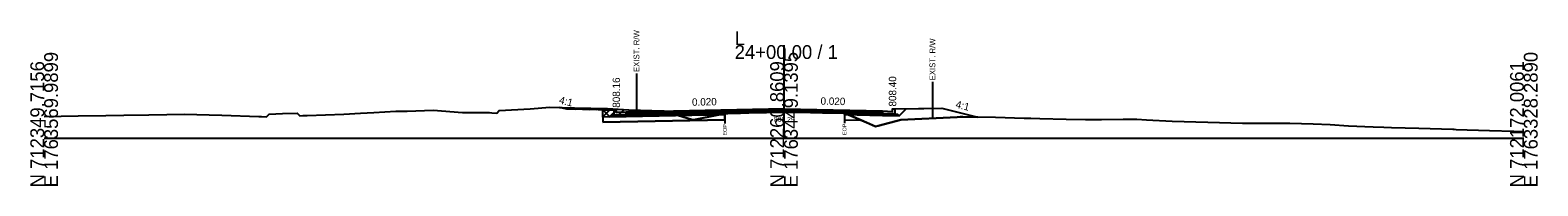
# Model space of a CAD drawing. Extents: x -26 to 5303, y -10 to 9578.
# Drawn here: x 997.2 to 1302.8, y 3990.3 to 4021.9 of the extents above; entities that cross this region are included whole.
import ezdxf

# ---------------------------------------------------------------- set-up
doc = ezdxf.new("R2010")
doc.units = 0
for name, color, linetype in [('Default', 7, 'Continuous'), ('Exist CMT Pavement', 7, 'Continuous'), ('Exist Cross Section Cell', 7, 'Continuous'), ('Exist XS Ground Line', 7, 'Continuous'), ('Old_Level_10', 7, 'Continuous'), ('Old_Level_3', 7, 'Continuous'), ('Prop CMT Conc Surface', 7, 'Continuous'), ('Prop CMT Concrete Structures', 7, 'Continuous'), ('Prop CMT Pvmt Course 1', 7, 'Continuous'), ('Prop CMT Pvmt Course 1 CG', 7, 'Continuous'), ('Prop CMT Pvmt Course 2', 7, 'Continuous'), ('Prop CMT Pvmt Course 3', 7, 'Continuous'), ('Prop CMT Pvmt Surface', 7, 'Continuous'), ('Prop CMT Slope Grass', 7, 'Continuous'), ('Prop CMT Subgrade Earthwork', 7, 'Continuous'), ('Prop Shade Light', 7, 'Continuous'), ('Prop XS Earthwork Shape', 7, 'Continuous'), ('Prop XS Hydro Elevations', 7, 'Continuous'), ('Prop XS SE Text', 7, 'Continuous'), ('Prop XS Side Slope Text', 7, 'Continuous'), ('Prop XS Wedging', 7, 'Continuous'), ('Scratch_Level_5', 7, 'Continuous')]:
    doc.layers.add(name, color=color, linetype=linetype)

msp = doc.modelspace()

# ---------------------------------------------------------------- linework, layer by layer
at = {"layer": 'Exist CMT Pavement'}
msp.add_lwpolyline([(1138.01, 4004.98), (1138.59, 4005), (1139.27, 4005.03), (1141.17, 4005.07), (1142.85, 4005.13), (1144.28, 4005.16), (1145.12, 4005.18), (1146.42, 4005.21), (1147.38, 4005.23), (1148.27, 4005.24), (1150, 4005.29), (1150.3, 4005.29), (1151.08, 4005.27), (1151.79, 4005.26), (1153.59, 4005.23), (1155.36, 4005.21), (1156.69, 4005.18), (1157.15, 4005.17), (1157.78, 4005.15), (1158.94, 4005.14), (1159.79, 4005.13), (1160.73, 4005.12), (1161.63, 4005.09), (1162.26, 4005.07), (1162.26, 4005.07)], dxfattribs=at)
at = {"layer": 'Exist Cross Section Cell'}
for p, q in [((1150, 4000), (1150, 4018.85)), ((1000, 4000), (1150, 4000)), ((1150, 4000), (1300, 4000))]:
    msp.add_line(p, q, dxfattribs=at)
at = {"layer": 'Exist XS Ground Line'}
msp.add_lwpolyline([(1000, 4004.41), (1006.9, 4004.51), (1012.49, 4004.61), (1016.17, 4004.67), (1021.2, 4004.73), (1024.9, 4004.78), (1028.36, 4004.82), (1036.02, 4004.66), (1043.49, 4004.41), (1044.04, 4004.38), (1045.11, 4004.34), (1045.65, 4004.85), (1048.33, 4004.98), (1051.32, 4005.04), (1051.82, 4004.54), (1052.42, 4004.57), (1053.32, 4004.61), (1060.77, 4004.88), (1064.13, 4005.03), (1066.82, 4005.2), (1071.28, 4005.46), (1073.6, 4005.47), (1078.88, 4005.67), (1084.8, 4005.2), (1090.28, 4005.16), (1090.73, 4005.13), (1091.78, 4005.08), (1092.28, 4005.58), (1098.51, 4005.95), (1102.52, 4006.28), (1107.49, 4006.15), (1114.2, 4005.99), (1118.54, 4005.74), (1125.55, 4005.5), (1131.24, 4003.79), (1131.65, 4003.68), (1137.45, 4004.88), (1138.01, 4004.98), (1138.59, 4005), (1139.27, 4005.03), (1141.17, 4005.07), (1141.93, 4005.09), (1144.28, 4005.16), (1145.12, 4005.18), (1146.42, 4005.21), (1147.38, 4005.23), (1148.27, 4005.24), (1150, 4005.29), (1150.3, 4005.29), (1151.08, 4005.27), (1151.79, 4005.26), (1153.59, 4005.23), (1155.36, 4005.21), (1156.69, 4005.18), (1157.78, 4005.15), (1158.94, 4005.14), (1159.79, 4005.13), (1160.73, 4005.12), (1161.63, 4005.09), (1162.26, 4005.07), (1166.73, 4003.13), (1168.57, 4002.38), (1169.09, 4002.51), (1173.66, 4003.68), (1185.08, 4004.26), (1185.74, 4004.3), (1186.28, 4004.29), (1192.9, 4004.23), (1198.7, 4004.02), (1200.05, 4004.02), (1201.89, 4003.97), (1207.2, 4003.85), (1211.11, 4003.79), (1214.36, 4003.79), (1218.78, 4003.86), (1221.51, 4003.82), (1223.52, 4003.72), (1228.67, 4003.43), (1235.94, 4003.21), (1242.97, 4003.04), (1248.35, 4003.04), (1252.54, 4003.02), (1257.28, 4002.89), (1260.76, 4002.76), (1264.43, 4002.5), (1269.43, 4002.27), (1271.59, 4002.2), (1273.18, 4002.16), (1278.74, 4002.03), (1285.59, 4001.79), (1285.9, 4001.78), (1286.31, 4001.76), (1293.05, 4001.51), (1298, 4001.4), (1300, 4001.34)], dxfattribs=at)
at = {"layer": 'Old_Level_10'}
for p, q in [((1120.09, 4013.09), (1120.09, 4005.69)), ((1180.09, 4011.41), (1180.09, 4004.01)), ((1138.01, 4004.98), (1138.01, 4002.93)), ((1162.26, 4005.07), (1162.26, 4003.02))]:
    msp.add_line(p, q, dxfattribs=at)
at = {"layer": 'Prop CMT Conc Surface'}
for points in [[(1116, 4005.16), (1116, 4005.66), (1115.5, 4005.66)], [(1118, 4005.28), (1116, 4005.16)], [(1170, 4005.52), (1172, 4005.4)], [(1172, 4005.4), (1172, 4005.9), (1172.5, 4005.9)]]:
    msp.add_lwpolyline(points, dxfattribs=at)
at = {"layer": 'Prop CMT Concrete Structures'}
for points in [[(1118, 4005.28), (1116, 4005.16), (1116, 4005.66), (1115.5, 4005.66)], [(1115.5, 4005.66), (1115.5, 4004.65), (1118, 4004.7)], [(1118, 4004.7), (1118, 4005.28)], [(1170, 4005.52), (1172, 4005.4), (1172, 4005.9), (1172.5, 4005.9)], [(1172.5, 4005.9), (1172.5, 4004.89), (1170, 4004.94)], [(1170, 4004.94), (1170, 4005.52)]]:
    msp.add_lwpolyline(points, dxfattribs=at)
at = {"layer": 'Prop CMT Pvmt Course 1'}
for points in [[(1150, 4005.92), (1118, 4005.28)], [(1118, 4005.03), (1138.01, 4005.43)], [(1118, 4005.28), (1118, 4005.03)], [(1138.01, 4005.43), (1150, 4005.67)], [(1138.01, 4005.43), (1138.01, 4005.43)], [(1150, 4005.67), (1150, 4005.92)], [(1150, 4005.92), (1170, 4005.52)], [(1150, 4005.67), (1150, 4005.67), (1150, 4005.67)], [(1162.26, 4005.43), (1150, 4005.67)], [(1170, 4005.27), (1162.26, 4005.43)], [(1162.26, 4005.43), (1162.26, 4005.43)], [(1170, 4005.52), (1170, 4005.27)]]:
    msp.add_lwpolyline(points, dxfattribs=at)
at = {"layer": 'Prop CMT Pvmt Course 1 CG'}
for points in [[(1118, 4004.7), (1115, 4004.64), (1114.66, 4004.3)], [(1118, 4004.37), (1118, 4004.7)], [(1170, 4004.94), (1173, 4004.88), (1173.34, 4004.54)], [(1170, 4004.61), (1170, 4004.94)], [(1173.34, 4004.54), (1170, 4004.61)], [(1114.66, 4004.3), (1118, 4004.37)]]:
    msp.add_lwpolyline(points, dxfattribs=at)
at = {"layer": 'Prop CMT Pvmt Course 2'}
for points in [[(1138.01, 4005.43), (1118, 4005.03)], [(1118, 4004.7), (1138.01, 4005.1)], [(1118, 4005.03), (1118, 4004.7)], [(1138.01, 4005.1), (1138.01, 4005.43)], [(1162.26, 4005.09), (1162.26, 4005.43)], [(1162.26, 4005.43), (1170, 4005.27)], [(1170, 4004.94), (1162.26, 4005.09)], [(1170, 4005.27), (1170, 4004.94)]]:
    msp.add_lwpolyline(points, dxfattribs=at)
at = {"layer": 'Prop CMT Pvmt Course 3'}
for points in [[(1138.01, 4005.1), (1118, 4004.7)], [(1118, 4004.37), (1138.01, 4004.77)], [(1118, 4004.7), (1118, 4004.37)], [(1138.01, 4004.77), (1138.01, 4005.1)], [(1162.26, 4005.09), (1170, 4004.94)], [(1162.26, 4004.76), (1162.26, 4005.09)], [(1170, 4004.61), (1162.26, 4004.76)], [(1170, 4004.94), (1170, 4004.61)]]:
    msp.add_lwpolyline(points, dxfattribs=at)
at = {"layer": 'Prop CMT Pvmt Surface'}
for points in [[(1150, 4005.92), (1118, 4005.28)], [(1150, 4005.92), (1170, 4005.52)]]:
    msp.add_lwpolyline(points, dxfattribs=at)
at = {"layer": 'Prop CMT Slope Grass'}
for points in [[(1115.5, 4005.66), (1106, 4005.85), (1104.5, 4006.23)], [(1172.5, 4005.9), (1182, 4006.09), (1189.32, 4004.26)]]:
    msp.add_lwpolyline(points, dxfattribs=at)
at = {"layer": 'Prop CMT Subgrade Earthwork'}
for p, q in [((1138.01, 4004.77), (1138.01, 4004.98)), ((1162.26, 4004.76), (1162.26, 4005.07))]:
    msp.add_line(p, q, dxfattribs=at)
for points in [[(1118, 4004.37), (1114.66, 4004.3), (1113.25, 4005.71)], [(1138.01, 4004.77), (1118, 4004.37)], [(1162.26, 4004.76), (1170, 4004.61)], [(1170, 4004.61), (1173.34, 4004.54), (1174.75, 4005.95)]]:
    msp.add_lwpolyline(points, dxfattribs=at)
at = {"layer": 'Prop Shade Light'}
for p, q in [((1128.61, 4004.58), (1118, 4004.37)), ((1138.01, 4004.77), (1136.78, 4004.74)), ((1138.01, 4004.77), (1138.01, 4003.73)), ((1138.01, 4003.73), (1138.01, 4004.77)), ((1162.26, 4004.76), (1162.26, 4003.72)), ((1162.26, 4004.76), (1162.26, 4003.72)), ((1163.01, 4004.75), (1162.26, 4004.76)), ((1165.51, 4003.66), (1163.01, 4004.75)), ((1114.66, 4004.3), (1113.25, 4004.27)), ((1113.25, 4004.27), (1113.25, 4003.23)), ((1113.25, 4004.27), (1113.25, 4003.23)), ((1113.25, 4003.23), (1138.01, 4003.73)), ((1162.26, 4003.72), (1165.51, 4003.66))]:
    msp.add_line(p, q, dxfattribs=at)
for points in [[(1138.01, 4004.77), (1113.25, 4004.27)], [(1136.78, 4004.74), (1131.65, 4003.68), (1131.24, 4003.79), (1128.61, 4004.58)], [(1138.01, 4003.73), (1113.25, 4003.23)], [(1118, 4004.37), (1114.66, 4004.3), (1114.66, 4004.3)], [(1162.26, 4003.72), (1165.51, 4003.66)]]:
    msp.add_lwpolyline(points, dxfattribs=at)
at = {"layer": 'Prop XS Earthwork Shape'}
for points in [[(1104.5, 4006.23), (1107.49, 4006.15), (1114.2, 4005.99), (1118.54, 4005.74), (1125.55, 4005.5), (1125.75, 4005.44), (1118, 4005.28), (1116, 4005.16), (1116, 4005.66), (1115.5, 4005.66), (1113.25, 4005.71), (1106, 4005.85)], [(1114.66, 4004.3), (1113.25, 4005.71), (1115.5, 4005.66), (1116, 4005.66), (1116, 4005.16), (1118, 4005.28), (1125.75, 4005.44), (1128.61, 4004.58), (1118, 4004.37)], [(1128.61, 4004.58), (1131.24, 4003.79), (1131.65, 4003.68), (1136.78, 4004.74)], [(1136.78, 4004.74), (1128.61, 4004.58), (1131.24, 4003.79), (1131.65, 4003.68)], [(1138.01, 4004.77), (1138.01, 4004.98), (1137.45, 4004.88), (1136.78, 4004.74)], [(1162.26, 4004.76), (1163.01, 4004.75), (1162.26, 4005.07)], [(1174.75, 4005.95), (1182, 4006.09), (1189.32, 4004.26), (1186.28, 4004.29), (1185.74, 4004.3), (1185.08, 4004.26), (1173.66, 4003.68), (1169.09, 4002.51), (1168.57, 4002.38), (1166.73, 4003.13), (1163.01, 4004.75), (1170, 4004.61), (1173.34, 4004.54)]]:
    msp.add_lwpolyline(points, close=True, dxfattribs=at)
at = {"layer": 'Prop XS Wedging'}
msp.add_lwpolyline([(1138.01, 4004.98), (1138.01, 4005.43), (1138.59, 4005.44), (1139.27, 4005.46), (1141.17, 4005.5), (1142.85, 4005.53), (1144.28, 4005.56), (1145.12, 4005.58), (1146.42, 4005.6), (1147.38, 4005.62), (1148.27, 4005.64), (1150, 4005.67), (1150.3, 4005.67), (1151.08, 4005.65), (1151.79, 4005.64), (1153.59, 4005.6), (1155.37, 4005.57), (1156.69, 4005.54), (1157.15, 4005.53), (1157.78, 4005.52), (1158.94, 4005.49), (1159.79, 4005.48), (1160.73, 4005.46), (1161.63, 4005.44), (1162.27, 4005.43), (1162.27, 4005.07), (1161.63, 4005.09), (1160.73, 4005.12), (1159.79, 4005.13), (1158.94, 4005.14), (1157.78, 4005.15), (1157.15, 4005.16), (1156.69, 4005.18), (1155.37, 4005.21), (1153.59, 4005.23), (1151.79, 4005.26), (1151.08, 4005.27), (1150.3, 4005.29), (1150, 4005.29), (1148.27, 4005.24), (1147.38, 4005.23), (1146.42, 4005.21), (1145.12, 4005.18), (1144.28, 4005.16), (1142.85, 4005.13), (1141.17, 4005.07), (1139.27, 4005.03), (1138.59, 4005)], close=True, dxfattribs=at)
at = {"layer": 'Scratch_Level_5'}
for p, q in [((1106, 4005.85), (1104.5, 4006.23)), ((1105.11, 4006.08), (1105.24, 4006.21)), ((1113.25, 4005.71), (1106, 4005.85)), ((1106.29, 4005.85), (1106.62, 4006.17)), ((1107.68, 4005.82), (1108, 4006.13)), ((1109.07, 4005.79), (1109.38, 4006.1)), ((1110.45, 4005.76), (1110.76, 4006.07)), ((1111.84, 4005.74), (1112.14, 4006.04)), ((1113.23, 4005.71), (1113.53, 4006.01)), ((1113.25, 4004.32), (1114.89, 4005.95)), ((1113.25, 4004.27), (1113.25, 4005.71)), ((1114.65, 4004.3), (1116.22, 4005.87)), ((1116.09, 4004.33), (1117.56, 4005.8)), ((1117.53, 4004.36), (1118.9, 4005.73)), ((1118.98, 4004.39), (1120.27, 4005.68)), ((1120.42, 4004.42), (1121.64, 4005.63)), ((1121.86, 4004.44), (1123, 4005.59)), ((1123.3, 4004.47), (1124.37, 4005.54)), ((1124.75, 4004.5), (1125.7, 4005.45)), ((1126.19, 4004.53), (1126.79, 4005.13)), ((1127.63, 4004.56), (1127.87, 4004.8))]:
    msp.add_line(p, q, dxfattribs=at)

# ---------------------------------------------------------------- texts
at = {"layer": 'Default'}
msp.add_text('-', height=0.0001, dxfattribs=at).set_placement((1000, 4000))
at = {"layer": 'Exist Cross Section Cell'}
for s, p in [('L', (1140, 4018.85)), ('24+00.00 / 1', (1140, 4016.05))]:
    msp.add_text(s, height=2.8, dxfattribs=at).set_placement(p)
for s, p in [('E 1763569.9899', (1002.8, 3990)), ('E 1763449.1395', (1152.8, 3990)), ('E 1763328.2890', (1302.8, 3990)), ('N 712349.7156', (1000, 3990)), ('N 712260.8609', (1150, 3990)), ('N 712172.0061', (1300, 3990))]:
    msp.add_text(s, height=2.8, rotation=90, dxfattribs=at).set_placement(p)
at = {"layer": 'Old_Level_10'}
for s, height, p in [('EXIST. R/W', 1.181, (1120.68, 4013.39)), ('EXIST. R/W', 1.181, (1180.68, 4011.71)), ('EOP', 0.787, (1138.4, 4000.53)), ('EOP', 0.787, (1162.66, 4000.62))]:
    msp.add_text(s, height=height, rotation=90, dxfattribs=at).set_placement(p)
at = {"layer": 'Old_Level_3'}
msp.add_text('808.29', height=1, dxfattribs=at).set_placement((1147.95, 4003.29))
at = {"layer": 'Prop XS Hydro Elevations'}
for s, p in [('808.16', (1116.75, 4006.16)), ('808.40', (1172.75, 4006.4))]:
    msp.add_text(s, height=1.5, rotation=90, dxfattribs=at).set_placement(p)
at = {"layer": 'Prop XS SE Text'}
for rotation, p in [(1.1458, (1131.36, 4006.55)), (358.8542, (1157.4, 4006.78))]:
    msp.add_text('0.020', height=1.5, rotation=rotation, dxfattribs=at).set_placement(p)
at = {"layer": 'Prop XS Side Slope Text'}
for p in [(1104.28, 4007.06), (1184.69, 4006.19)]:
    msp.add_text('4:1', height=1.5, rotation=345.9638, dxfattribs=at).set_placement(p)

doc.saveas('drawing.dxf')
